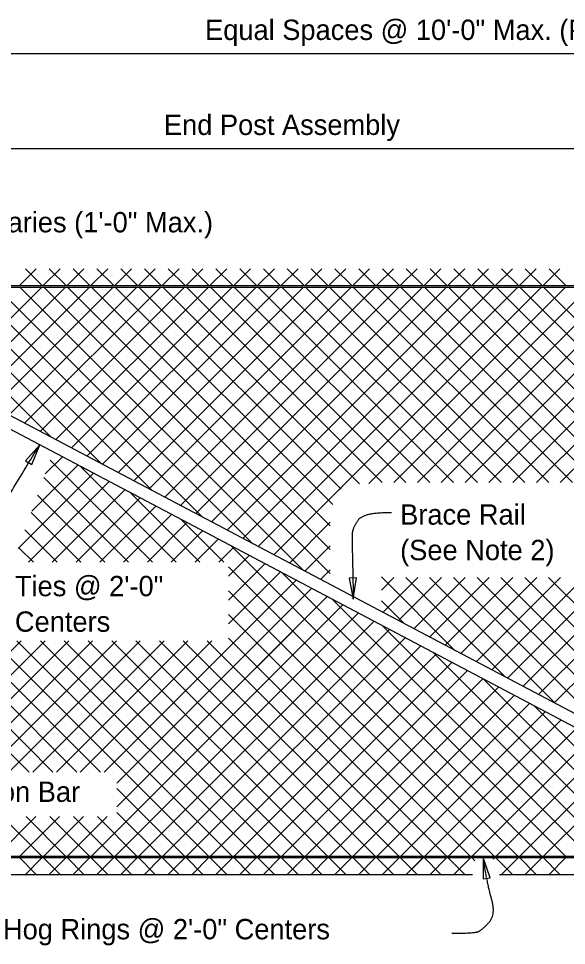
# Model space of a CAD drawing. Extents: x 0 to 41, y -96 to 25.
# Drawn here: x 6.74 to 12.16, y -79.57 to -70.39 of the extents above; entities that cross this region are included whole.
import ezdxf

# ---------------------------------------------------------------- set-up
doc = ezdxf.new("R2010")
doc.units = 0
for name, color, linetype in [('Dimension', 7, 'Continuous'), ('Miscellaneous', 7, 'Continuous'), ('SteelMisc', 7, 'Continuous'), ('SupstrConc', 7, 'Continuous'), ('TextStructures', 7, 'Continuous')]:
    doc.layers.add(name, color=color, linetype=linetype)

msp = doc.modelspace()

# ---------------------------------------------------------------- linework, layer by layer
at = {"layer": 'Dimension'}
for p, q in [((0.2352, -70.732), (13.615, -70.732)), ((4.615, -71.673), (14.615, -71.673))]:
    msp.add_line(p, q, dxfattribs=at)
for points in [[(6.945, -74.607), (6.8059, -74.766), (6.8661, -74.8029)], [(10.0503, -76.1347), (10.0815, -75.9258), (10.011, -75.9272)], [(11.336, -78.6964), (11.3376, -78.9076), (11.4071, -78.8953)]]:
    msp.add_lwpolyline(points, close=True, dxfattribs=at)
for points in [[(6.6174, -76.0066), (6.4865, -76.0207), (6.3036, -75.9534), (6.3121, -75.6268), (6.945, -74.607)], [(10.4281, -75.2824), (10.1586, -75.2743), (10.0405, -75.4327), (10.0376, -75.5539), (10.0422, -75.7217), (10.0503, -76.1347)], [(11.0247, -79.4433), (11.2476, -79.4469), (11.3325, -79.4079), (11.4633, -79.2592), (11.3785, -78.9618), (11.336, -78.6965)]]:
    msp.add_open_spline(points, degree=2, dxfattribs=at)
at = {"layer": 'Miscellaneous'}
for p, q in [((6.745, -73.0298), (6.9116, -72.8631)), ((6.8042, -72.8631), (6.9709, -73.0298)), ((6.9807, -73.0298), (7.1473, -72.8631)), ((7.0399, -72.8631), (7.2066, -73.0298)), ((7.2164, -73.0298), (7.383, -72.8631)), ((7.2756, -72.8631), (7.4423, -73.0298)), ((7.4521, -73.0298), (7.6187, -72.8631)), ((7.5113, -72.8631), (7.678, -73.0298)), ((7.6878, -73.0298), (7.8544, -72.8631)), ((7.747, -72.8631), (7.9137, -73.0298)), ((7.9235, -73.0298), (8.0901, -72.8631)), ((7.9827, -72.8631), (8.1494, -73.0298)), ((8.1592, -73.0298), (8.3258, -72.8631)), ((8.2184, -72.8631), (8.3851, -73.0298)), ((8.3949, -73.0298), (8.5615, -72.8631)), ((8.4541, -72.8631), (8.6208, -73.0298)), ((8.6306, -73.0298), (8.7972, -72.8631)), ((8.6898, -72.8631), (8.8565, -73.0298)), ((8.8663, -73.0298), (9.0329, -72.8631)), ((8.9255, -72.8631), (9.0922, -73.0298)), ((9.102, -73.0298), (9.2687, -72.8631)), ((9.1612, -72.8631), (9.3279, -73.0298)), ((9.3377, -73.0298), (9.5044, -72.8631)), ((9.3969, -72.8631), (9.5636, -73.0298)), ((9.5734, -73.0298), (9.7401, -72.8631)), ((9.6326, -72.8631), (9.7993, -73.0298)), ((9.8091, -73.0298), (9.9758, -72.8631)), ((9.8683, -72.8631), (10.035, -73.0298)), ((10.0448, -73.0298), (10.2115, -72.8631)), ((10.104, -72.8631), (10.2707, -73.0298)), ((10.2805, -73.0298), (10.4472, -72.8631)), ((10.3397, -72.8631), (10.5064, -73.0298)), ((10.5162, -73.0298), (10.6829, -72.8631)), ((10.5754, -72.8631), (10.7421, -73.0298)), ((10.7519, -73.0298), (10.9186, -72.8631)), ((10.8111, -72.8631), (10.9778, -73.0298)), ((10.9876, -73.0298), (11.1543, -72.8631)), ((11.0468, -72.8631), (11.2135, -73.0298)), ((11.2233, -73.0298), (11.39, -72.8631)), ((11.2825, -72.8631), (11.4492, -73.0298)), ((11.459, -73.0298), (11.6257, -72.8631)), ((11.5182, -72.8631), (11.6849, -73.0298)), ((11.6947, -73.0298), (11.8614, -72.8631)), ((11.7539, -72.8631), (11.9206, -73.0298)), ((11.9304, -73.0298), (12.0971, -72.8631)), ((11.9896, -72.8631), (12.1563, -73.0298)), ((5.8071, -73.0445), (7.5577, -74.7951)), ((6.0252, -73.9852), (6.9659, -73.0445)), ((6.0428, -73.0445), (8.0575, -75.0593)), ((6.1794, -74.0667), (7.2016, -73.0445)), ((6.2785, -73.0445), (8.5574, -75.3234)), ((6.3336, -74.1482), (7.4373, -73.0445)), ((6.4878, -74.2297), (7.673, -73.0445)), ((6.5142, -73.0445), (9.0572, -75.5876)), ((6.642, -74.3112), (7.9087, -73.0445)), ((6.7499, -73.0445), (9.5571, -75.8517)), ((6.7962, -74.3927), (8.1444, -73.0445)), ((6.9504, -74.4742), (8.3801, -73.0445)), ((6.9856, -73.0445), (9.8224, -75.8813)), ((7.1046, -74.5557), (8.6158, -73.0445)), ((7.2213, -73.0445), (9.8224, -75.6456)), ((7.2589, -74.6372), (8.8515, -73.0445)), ((7.4131, -74.7187), (9.0872, -73.0445)), ((7.457, -73.0445), (9.8224, -75.4099)), ((7.5673, -74.8002), (9.3229, -73.0445)), ((7.6927, -73.0445), (9.8467, -75.1985)), ((7.7215, -74.8817), (9.5586, -73.0445)), ((7.8757, -74.9632), (9.7943, -73.0445)), ((7.9284, -73.0445), (9.9312, -75.0473)), ((8.0299, -75.0446), (10.03, -73.0445)), ((8.1641, -73.0445), (10.1124, -74.9928)), ((8.1841, -75.1261), (10.2657, -73.0445)), ((8.3383, -75.2076), (10.5014, -73.0445)), ((8.3998, -73.0445), (10.3365, -74.9812)), ((8.4925, -75.2891), (10.7372, -73.0445)), ((8.6355, -73.0445), (10.5722, -74.9812)), ((8.6467, -75.3706), (10.9729, -73.0445)), ((8.8009, -75.4521), (11.2086, -73.0445)), ((8.8712, -73.0445), (10.8079, -74.9812)), ((8.9552, -75.5336), (11.4443, -73.0445)), ((9.1069, -73.0445), (11.0436, -74.9812)), ((9.1094, -75.6151), (11.68, -73.0445)), ((9.2636, -75.6966), (11.9157, -73.0445)), ((9.3426, -73.0445), (11.2793, -74.9812)), ((9.5783, -73.0445), (11.515, -74.9812)), ((9.814, -73.0445), (11.7507, -74.9812)), ((10.0497, -73.0445), (11.9864, -74.9812)), ((10.2043, -74.9916), (12.1514, -73.0445)), ((10.2854, -73.0445), (12.2221, -74.9812)), ((10.4504, -74.9812), (12.3871, -73.0445)), ((10.5211, -73.0445), (14.4692, -76.9926)), ((10.6861, -74.9812), (12.6228, -73.0445)), ((10.7568, -73.0445), (14.4692, -76.7569)), ((10.9218, -74.9812), (12.8585, -73.0445)), ((10.9925, -73.0445), (14.4692, -76.5212)), ((11.1575, -74.9812), (13.0942, -73.0445)), ((11.2282, -73.0445), (14.4692, -76.2855)), ((11.3932, -74.9812), (13.3299, -73.0445)), ((11.4639, -73.0445), (14.4692, -76.0498)), ((11.6289, -74.9812), (13.5656, -73.0445)), ((11.6996, -73.0445), (14.4692, -75.8141)), ((11.8646, -74.9812), (13.8013, -73.0445)), ((11.9353, -73.0445), (14.4692, -75.5784)), ((12.1003, -74.9812), (14.037, -73.0445)), ((5.7518, -73.2249), (7.0578, -74.531)), ((11.5767, -76.919), (14.4692, -74.0265)), ((11.7309, -77.0005), (14.4692, -74.2622)), ((11.8851, -77.082), (14.4692, -74.4979)), ((7.0006, -74.8954), (7.1701, -74.7259)), ((12.0393, -77.1635), (14.4692, -74.7336)), ((6.8661, -75.2656), (7.3243, -74.8074)), ((7.0502, -74.759), (8.0609, -75.7697)), ((7.3455, -74.8186), (8.2966, -75.7697)), ((6.7317, -75.6358), (7.4785, -74.8889)), ((4.8859, -74.9517), (8.6158, -78.6817)), ((6.8334, -75.7697), (7.6327, -74.9704)), ((6.9874, -74.9319), (7.8252, -75.7697)), ((7.0691, -75.7697), (7.7869, -75.0519)), ((7.8453, -75.0828), (8.5323, -75.7697)), ((4.8859, -75.1874), (7.5472, -77.8488)), ((6.9246, -75.1048), (7.5895, -75.7697)), ((7.3048, -75.7697), (7.9412, -75.1334)), ((6.8618, -75.2777), (7.3538, -75.7697)), ((7.5405, -75.7697), (8.0954, -75.2149)), ((7.7762, -75.7697), (8.2496, -75.2964)), ((8.3452, -75.3469), (8.768, -75.7697)), ((9.4178, -75.7781), (9.8224, -75.3735)), ((4.8859, -75.4231), (7.3115, -77.8488)), ((6.7989, -75.4506), (7.1181, -75.7697)), ((8.0119, -75.7697), (8.4038, -75.3779)), ((8.2476, -75.7697), (8.558, -75.4594)), ((8.4833, -75.7697), (8.7122, -75.5408)), ((6.7361, -75.6235), (6.8824, -75.7697)), ((8.719, -75.7697), (8.8664, -75.6223)), ((8.845, -75.611), (11.9157, -78.6817)), ((9.572, -75.8596), (9.8224, -75.6092)), ((4.8859, -75.6588), (7.0758, -77.8488)), ((8.8145, -75.9099), (9.0206, -75.7038)), ((8.8145, -76.1456), (9.1748, -75.7853)), ((8.8145, -75.8163), (11.68, -78.6817)), ((4.8876, -75.8963), (6.8401, -77.8488)), ((8.8145, -76.3813), (9.3291, -75.8668)), ((9.3449, -75.8752), (12.1514, -78.6817)), ((9.7262, -75.9411), (9.8224, -75.8449)), ((10.3288, -75.9163), (11.0567, -76.6442)), ((10.3288, -76.0456), (10.4524, -75.922)), ((10.343, -76.267), (10.6881, -75.922)), ((10.4973, -76.3485), (10.9238, -75.922)), ((10.5702, -75.922), (11.5565, -76.9083)), ((10.6515, -76.43), (11.1595, -75.922)), ((10.8057, -76.5115), (11.3952, -75.922)), ((10.8059, -75.922), (12.0564, -77.1725)), ((10.9599, -76.593), (11.6309, -75.922)), ((11.0416, -75.922), (12.5562, -77.4366)), ((11.1141, -76.6745), (11.8666, -75.922)), ((11.2683, -76.756), (12.1023, -75.922)), ((11.2773, -75.922), (13.0561, -77.7008)), ((11.4225, -76.8375), (12.3341, -75.9259)), ((11.513, -75.922), (13.5559, -77.9649)), ((11.7487, -75.922), (14.0558, -78.2291)), ((11.9844, -75.922), (14.4692, -78.4068)), ((7.5828, -77.8488), (9.4833, -75.9483)), ((7.7103, -77.957), (9.6375, -76.0298)), ((8.8145, -76.052), (11.4443, -78.6817)), ((7.457, -78.6817), (9.9459, -76.1928)), ((7.7103, -78.1927), (9.7917, -76.1113)), ((9.0917, -76.8113), (9.7917, -76.1113)), ((9.0917, -77.047), (9.9459, -76.1928)), ((9.8447, -76.1393), (12.3871, -78.6817)), ((10.3288, -76.152), (10.5568, -76.38)), ((7.6927, -78.6817), (10.1001, -76.2743)), ((8.8145, -76.2877), (11.2086, -78.6817)), ((9.0917, -77.2827), (10.1001, -76.2743)), ((7.9284, -78.6817), (10.2543, -76.3558)), ((8.1641, -78.6817), (10.4085, -76.4373)), ((10.3445, -76.4034), (12.6228, -78.6817)), ((5.7273, -77.5829), (6.7626, -76.5476)), ((5.8187, -77.7273), (6.9983, -76.5476)), ((5.9329, -77.8488), (7.234, -76.5476)), ((6.1686, -77.8488), (7.4697, -76.5476)), ((6.4043, -77.8488), (7.7055, -76.5476)), ((6.64, -77.8488), (7.9412, -76.5476)), ((6.7175, -76.5476), (8.8515, -78.6817)), ((6.8757, -77.8488), (8.1769, -76.5476)), ((6.9532, -76.5476), (9.0872, -78.6817)), ((7.1114, -77.8488), (8.4126, -76.5476)), ((7.1889, -76.5476), (9.3229, -78.6817)), ((7.3471, -77.8488), (8.6483, -76.5476)), ((7.4246, -76.5476), (9.5586, -78.6817)), ((7.6603, -76.5476), (9.7943, -78.6817)), ((7.896, -76.5476), (10.03, -78.6817)), ((8.1317, -76.5476), (10.2657, -78.6817)), ((8.3674, -76.5476), (10.5014, -78.6817)), ((8.3998, -78.6817), (10.5627, -76.5187)), ((8.6031, -76.5476), (10.7372, -78.6817)), ((8.8145, -76.5234), (10.9729, -78.6817)), ((8.6355, -78.6817), (10.717, -76.6002)), ((8.8712, -78.6817), (10.8712, -76.6817)), ((10.8444, -76.6676), (12.8585, -78.6817)), ((9.1069, -78.6817), (11.0254, -76.7632)), ((9.3426, -78.6817), (11.1796, -76.8447)), ((9.5783, -78.6817), (11.3338, -76.9262)), ((11.3442, -76.9317), (13.0942, -78.6817)), ((9.814, -78.6817), (11.488, -77.0077)), ((10.0497, -78.6817), (11.6422, -77.0892)), ((10.2854, -78.6817), (11.7964, -77.1707)), ((11.8441, -77.1959), (13.3299, -78.6817)), ((10.5211, -78.6817), (11.9506, -77.2522)), ((10.639, -78.7995), (12.1048, -77.3337)), ((10.9925, -78.6817), (12.2591, -77.4152)), ((11.2282, -78.6817), (12.4133, -77.4966)), ((11.4639, -78.6817), (12.5675, -77.5781)), ((11.6996, -78.6817), (12.7217, -77.6596)), ((11.9353, -78.6817), (12.8759, -77.7411)), ((7.7103, -78.0119), (8.3801, -78.6817)), ((6.5142, -78.6817), (6.9059, -78.29)), ((6.5742, -78.29), (6.9659, -78.6817)), ((6.7499, -78.6817), (7.1416, -78.29)), ((6.8099, -78.29), (7.2016, -78.6817)), ((6.9856, -78.6817), (7.3773, -78.29)), ((7.0456, -78.29), (7.4373, -78.6817)), ((7.2213, -78.6817), (7.613, -78.29)), ((7.2813, -78.29), (7.673, -78.6817)), ((7.517, -78.29), (7.9087, -78.6817)), ((7.7103, -78.2476), (8.1444, -78.6817)), ((6.745, -78.6964), (6.9116, -78.8631)), ((6.8042, -78.8631), (6.9709, -78.6964)), ((6.9807, -78.6964), (7.1473, -78.8631)), ((7.0399, -78.8631), (7.2066, -78.6964)), ((7.2164, -78.6964), (7.383, -78.8631)), ((7.2756, -78.8631), (7.4423, -78.6964)), ((7.4521, -78.6964), (7.6187, -78.8631)), ((7.5113, -78.8631), (7.678, -78.6964)), ((7.6878, -78.6964), (7.8544, -78.8631)), ((7.747, -78.8631), (7.9137, -78.6964)), ((7.9235, -78.6964), (8.0901, -78.8631)), ((7.9827, -78.8631), (8.1494, -78.6964)), ((8.1592, -78.6964), (8.3258, -78.8631)), ((8.2184, -78.8631), (8.3851, -78.6964)), ((8.3949, -78.6964), (8.5615, -78.8631)), ((8.4541, -78.8631), (8.6208, -78.6964)), ((8.6306, -78.6964), (8.7972, -78.8631)), ((8.6898, -78.8631), (8.8565, -78.6964)), ((8.8663, -78.6964), (9.0329, -78.8631)), ((8.9255, -78.8631), (9.0922, -78.6964)), ((9.102, -78.6964), (9.2687, -78.8631)), ((9.1612, -78.8631), (9.3279, -78.6964)), ((9.3377, -78.6964), (9.5044, -78.8631)), ((9.3969, -78.8631), (9.5636, -78.6964)), ((9.5734, -78.6964), (9.7401, -78.8631)), ((9.6326, -78.8631), (9.7993, -78.6964)), ((9.8091, -78.6964), (9.9758, -78.8631)), ((9.8683, -78.8631), (10.035, -78.6964)), ((10.0448, -78.6964), (10.2115, -78.8631)), ((10.104, -78.8631), (10.2707, -78.6964)), ((10.2805, -78.6964), (10.4472, -78.8631)), ((10.3397, -78.8631), (10.5064, -78.6964)), ((10.5162, -78.6964), (10.6829, -78.8631)), ((10.5754, -78.8631), (10.7421, -78.6964)), ((10.7519, -78.6964), (10.9186, -78.8631)), ((10.8111, -78.8631), (10.9778, -78.6964)), ((10.9876, -78.6964), (11.1543, -78.8631)), ((11.0468, -78.8631), (11.2135, -78.6964)), ((11.2233, -78.6964), (11.2544, -78.7276)), ((11.4351, -78.7105), (11.4492, -78.6964)), ((11.459, -78.6964), (11.6257, -78.8631)), ((11.5182, -78.8631), (11.6849, -78.6964)), ((11.6947, -78.6964), (11.8614, -78.8631)), ((11.7539, -78.8631), (11.9206, -78.6964)), ((11.9304, -78.6964), (12.0971, -78.8631)), ((11.9896, -78.8631), (12.1563, -78.6964))]:
    msp.add_line(p, q, dxfattribs=at)
at = {"layer": 'SteelMisc'}
for p, q in [((5.8052, -73.0298), (14.2941, -73.0298)), ((5.8052, -73.0445), (14.3207, -73.0445)), ((14.2677, -78.341), (5.0181, -73.453)), ((14.2117, -78.447), (4.962, -73.5591)), ((4.923, -78.6964), (14.3207, -78.6964)), ((4.9243, -78.6817), (14.2941, -78.6817))]:
    msp.add_line(p, q, dxfattribs=at)
at = {"layer": 'SupstrConc'}
for p, q in [((4.7609, -78.8631), (11.2293, -78.8631)), ((11.4981, -78.8631), (14.4692, -78.8631))]:
    msp.add_line(p, q, dxfattribs=at)

# ---------------------------------------------------------------- texts
at = {"layer": 'Dimension'}
for s, p in [('Ties @ 2\'-0" ', (6.6999, -76.1071)), ('Centers', (6.6999, -76.4591))]:
    msp.add_text(s, height=0.2016, dxfattribs=at).set_placement(p)
at = {"layer": 'TextStructures'}
for s, p in [('Equal Spaces @ 10\'-0" Max. (Posts may be shifted minimally to meet required clearances)', (8.5826, -70.5974)), ('End Post Assembly', (8.1753, -71.5384)), ('Varies (1\'-0" Max.)', (6.4474, -72.503)), ('Brace Rail', (10.5146, -75.3981)), ('(See Note 2)', (10.5146, -75.7501)), ('Tension Bar', (5.892, -78.1443)), ('Hog Rings @ 2\'-0" Centers', (6.5816, -79.5053))]:
    msp.add_text(s, height=0.2016, dxfattribs=at).set_placement(p)

doc.saveas('drawing.dxf')
